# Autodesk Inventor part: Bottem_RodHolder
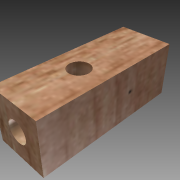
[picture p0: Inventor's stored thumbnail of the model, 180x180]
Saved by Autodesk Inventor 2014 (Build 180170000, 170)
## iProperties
Created: 2013-12
Part Number: Bottem_RodHolder
Material: Birch
Document SubType Name: Modeling
Designer: Bram
Density: 0.512 g/cm^3
Appearance: Birch - Natural Medium Gloss
Author: Bram
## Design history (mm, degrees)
sketch "Sketch1"
  geometry: L1 (0, 0)-(20, 0); L2 (20, 0)-(20, 33); L3 (20, 33)-(0, 33); L4 (0, 33)-(0, 0); L5 (6, 15)-(6, 0); L6 (14, 15)-(14, 0); L7 (6, 15)-(14, 15); L8 (10, 0)-(10, 23); C1 r 4 at (10, 23)
  constraints: 16 end point, 5 perpendicular, 2 parallel, 2 point on line, 1 centre point, 1 coincident, 1 horizontal, 1 midpoint
  dimensions: "d5" = 23 distance of L8.start L8.end; "d6" = 8 diameter of C1
extrude "Extrusion1" new body sketch "Sketch1" distance "d7" = 20; taper "d8" = 0 deg
sketch "Sketch2"
  geometry: C1 r 4 at (10, 10)
  constraints: 1 centre point
  dimensions: "d9" = 8 diameter of C1
extrude "Extrusion2" cut sketch "Sketch2" distance "d10" = 15; taper "d11" = 0 deg
sketch "Sketch3"
  geometry: L1 (20, 0)-(0, 0) reference; L2 (0, 0)-(0, -20) reference; L3 (20, -20)-(0, -20) reference; L4 (20, 0)-(20, -20) reference
extrude "Extrusion3" join sketch "Sketch3" distance "d12" = 22; taper "d13" = 0 deg
body "Solid1"
